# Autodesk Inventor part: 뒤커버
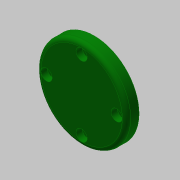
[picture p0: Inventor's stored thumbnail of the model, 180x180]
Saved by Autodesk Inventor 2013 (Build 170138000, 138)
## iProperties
Created: 2020-07
Part Number: 뒤커버
Material: 알루미늄 6061
Document SubType Name: Modeling
Designer: mduedu
Density: 1 g/cm^3
Author: mduedu
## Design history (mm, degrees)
sketch "스케치1"
  geometry: L1 (0, 0)-(9, 0); L2 (9, 0)-(9, 32); L3 (9, 32)-(0, 32); L4 (0, 32)-(0, 0); L5 (9, 0)-(12, 0); L6 (12, 0)-(12, 20); L7 (12, 20)-(9, 20); L8 (9, 20)-(9, 0)
  constraints: 16 end point, 4 parallel, 2 horizontal, 2 perpendicular
  dimensions: "d0" = 64 diameter of L3 L1; "d2" = 40 diameter of L7 L5; "d3" = 3 distance of L6.end L7.end; "d4" = 12 distance between parallel lines of L4 L6
revolve "회전1" sketch "스케치1" stored, may be unused: angle "d5" = 90 deg
sketch "스케치2"
  geometry: C1 r 15 at (0, 0); 1 further point
  constraints: 1 centre point, 1 coincident
  dimensions: "d6" = 30 diameter of C1
extrude "돌출1" cut sketch "스케치2" distance "d7" = 6; taper "d8" = 0 deg
fillet "모깎기1" dims "d9" = 3
fillet "모깎기2" dims "d10" = 3
chamfer "모따기1" distance "d11" = 1; stored, may be unused: second distance "d12" = 2, angle "d13" = 45 deg
sketch "스케치3" dims "d14" = 50
  geometry: 3 further points
  constraints: 2 vertical alignment, 1 coincident, 2 other
hole "구멍1" sketch "스케치3" at (0, 25) diameter "d15" = 4.5; stored, may be unused: countersink angle "d19" = 90 deg, drill point angle "d21" = 118 deg; dims "d16" = 6, "d17" = 8, "d18" = 4.4, "d20" = 8
node "솔리드1"
pattern_circular "원형 패턴1" dims angle "d23" = 360 deg
